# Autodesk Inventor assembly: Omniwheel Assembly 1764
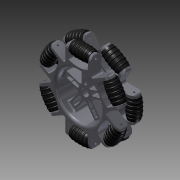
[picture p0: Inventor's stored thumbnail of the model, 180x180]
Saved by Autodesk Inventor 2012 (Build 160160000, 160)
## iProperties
Created: 2007-11
Part Number: Omniwheel Assembly 1764
Document SubType Name: Assembly
Designer: lwoods
Mass: 807.037 g
Surface Area: 1296.28 cm^2
Volume: 334.333 cm^3
Density: 2.41387 g/cm^3
Author: lwoods
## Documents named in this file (4)
- R:\CAD Archives\Wheels_1764\Omniwheel_1764\Omniwheel_Assembly_1764.iam
- R:\CAD Archives\Wheels_1764\Omniwheel_1764\Roller_Axle_V4_1764.ipt
- R:\CAD Archives\Wheels_1764\Omniwheel_1764\Omnidrive_1764.ipt
- R:\CAD Archives\Wheels_1764\Omniwheel_1764\Roller_Assembly_1764.iam
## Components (25 placed, 3 different names)
1. Omnidrive_1764:1 — Insert:1, Insert:2, Insert:3, Insert:4, Insert:5, Insert:6, Insert:7, Insert:8, Insert:9, Insert:10, Insert:11, Insert:12, Insert:16, Insert:17, Insert:19, Insert:20
2. Roller_Axle_V4_1764:1 — Insert:11, Insert:24
3. Roller_Axle_V4_1764:2 — Insert:8
4. Roller_Axle_V4_1764:3 — Insert:12, Insert:23
5. Roller_Axle_V4_1764:4 — Insert:10, Insert:22
6. Roller_Axle_V4_1764:5 — Insert:3, Insert:14
7. Roller_Axle_V4_1764:6 — Insert:4, Insert:18
8. Roller_Axle_V4_1764:7 — Insert:6
9. Roller_Axle_V4_1764:8 — Insert:2
10. Roller_Axle_V4_1764:9 — Insert:1, Insert:13
11. Roller_Axle_V4_1764:10 — Insert:5
12. Roller_Axle_V4_1764:11 — Insert:9, Insert:15
13. Roller_Axle_V4_1764:12 — Insert:7, Insert:21
14. Roller_Assembly_1764:1 [sub-assembly] — Insert:18
15. Roller_Assembly_1764:2 [sub-assembly] — Insert:20
16. Roller_Assembly_1764:3 [sub-assembly] — Insert:17
17. Roller_Assembly_1764:4 [sub-assembly] — Insert:19
18. Roller_Assembly_1764:5 [sub-assembly] — Insert:21
19. Roller_Assembly_1764:6 [sub-assembly] — Insert:22
20. Roller_Assembly_1764:7 [sub-assembly] — Insert:23
21. Roller_Assembly_1764:8 [sub-assembly] — Insert:24
22. Roller_Assembly_1764:9 [sub-assembly] — Insert:16
23. Roller_Assembly_1764:10 [sub-assembly] — Insert:15
24. Roller_Assembly_1764:11 [sub-assembly] — Insert:13
25. Roller_Assembly_1764:12 [sub-assembly] — Insert:14
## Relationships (24: Insert 24)
- Insert:1: Omnidrive_1764:1 ↔ Roller_Axle_V4_1764:9
- Insert:2: Omnidrive_1764:1 ↔ Roller_Axle_V4_1764:8
- Insert:3: Omnidrive_1764:1 ↔ Roller_Axle_V4_1764:5
- Insert:4: Omnidrive_1764:1 ↔ Roller_Axle_V4_1764:6
- Insert:5: Omnidrive_1764:1 ↔ Roller_Axle_V4_1764:10
- Insert:6: Omnidrive_1764:1 ↔ Roller_Axle_V4_1764:7
- Insert:7: Omnidrive_1764:1 ↔ Roller_Axle_V4_1764:12
- Insert:8: Omnidrive_1764:1 ↔ Roller_Axle_V4_1764:2
- Insert:9: Omnidrive_1764:1 ↔ Roller_Axle_V4_1764:11
- Insert:10: Omnidrive_1764:1 ↔ Roller_Axle_V4_1764:4
- Insert:11: Omnidrive_1764:1 ↔ Roller_Axle_V4_1764:1
- Insert:12: Omnidrive_1764:1 ↔ Roller_Axle_V4_1764:3
- Insert:13: Roller_Axle_V4_1764:9 ↔ Roller_Assembly_1764:11
- Insert:14: Roller_Axle_V4_1764:5 ↔ Roller_Assembly_1764:12
- Insert:15: Roller_Axle_V4_1764:11 ↔ Roller_Assembly_1764:10
- Insert:16: Omnidrive_1764:1 ↔ Roller_Assembly_1764:9
- Insert:17: Omnidrive_1764:1 ↔ Roller_Assembly_1764:3
- Insert:18: Roller_Axle_V4_1764:6 ↔ Roller_Assembly_1764:1
- Insert:19: Omnidrive_1764:1 ↔ Roller_Assembly_1764:4
- Insert:20: Omnidrive_1764:1 ↔ Roller_Assembly_1764:2
- Insert:21: Roller_Axle_V4_1764:12 ↔ Roller_Assembly_1764:5
- Insert:22: Roller_Axle_V4_1764:4 ↔ Roller_Assembly_1764:6
- Insert:23: Roller_Axle_V4_1764:3 ↔ Roller_Assembly_1764:7
- Insert:24: Roller_Axle_V4_1764:1 ↔ Roller_Assembly_1764:8
